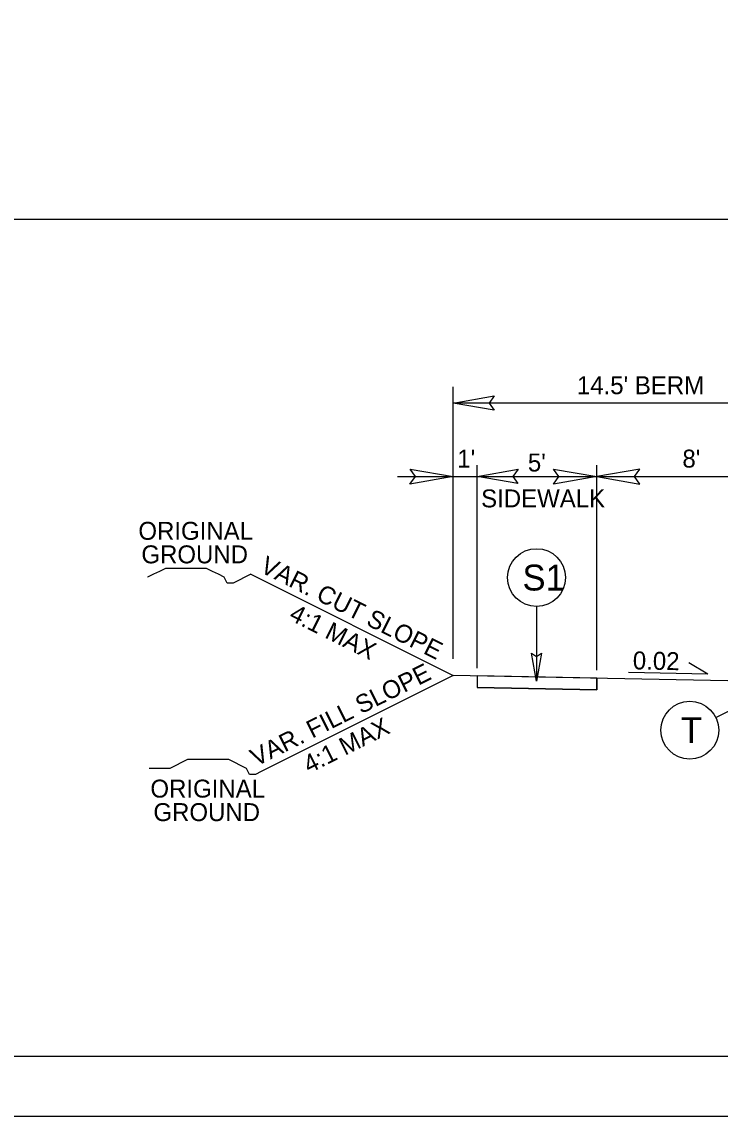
# Model space of a CAD drawing. Extents: x 1487909 to 1489267, y 497866 to 499814.
# Drawn here: x 1488926.44 to 1488955.62, y 498107.09 to 498152.83 of the extents above; entities that cross this region are included whole.
import ezdxf

# ---------------------------------------------------------------- set-up
doc = ezdxf.new("R2010")
doc.units = 0
for name, color, linetype in [('Prop Conc 4in Sidewalk', 7, 'Continuous'), ('Prop Dimension', 7, 'Continuous'), ('Prop Dimension Text', 7, 'Continuous'), ('Prop Shade Light', 7, 'Continuous'), ('Prop Terminator CELL', 7, 'Continuous'), ('Scratch_Level_1', 7, 'Continuous'), ('Sheet Plot Border Outside CELL', 7, 'Continuous'), ('Sheet Typical CELL', 7, 'Continuous'), ('Typical Hinge Slope Arterial CELL', 7, 'Continuous'), ('Typical ID Circle CELL', 7, 'Continuous'), ('Typical Pavement Slope CELL', 7, 'Continuous'), ('Typical Pavement Slope Information CELL', 7, 'Continuous'), ('Typical Terminator CELL', 7, 'Continuous'), ('Typical Text ID Circle CELL', 7, 'Continuous')]:
    doc.layers.add(name, color=color, linetype=linetype)

msp = doc.modelspace()

# ---------------------------------------------------------------- linework, layer by layer
at = {"layer": 'Prop Conc 4in Sidewalk'}
for p, q in [((1488950.464, 498125.387), (1488945.464, 498125.487)), ((1488945.464, 498125.487), (1488945.464, 498125.005)), ((1488950.464, 498124.905), (1488945.464, 498125.005)), ((1488950.464, 498125.387), (1488950.464, 498124.905))]:
    msp.add_line(p, q, dxfattribs=at)
at = {"layer": 'Prop Dimension'}
for p, q in [((1488944.464, 498126.203), (1488944.464, 498137.572)), ((1488958.964, 498136.891), (1488944.464, 498136.891)), ((1488945.464, 498125.808), (1488945.464, 498134.293)), ((1488950.464, 498125.73), (1488950.464, 498134.293)), ((1488942.133, 498133.822), (1488944.464, 498133.822)), ((1488944.464, 498133.822), (1488945.464, 498133.822)), ((1488945.464, 498133.822), (1488950.464, 498133.822)), ((1488950.464, 498133.822), (1488958.464, 498133.822))]:
    msp.add_line(p, q, dxfattribs=at)
at = {"layer": 'Prop Shade Light'}
for p, q in [((1488950.464, 498125.387), (1488945.464, 498125.487)), ((1488945.464, 498125.487), (1488945.464, 498125.005)), ((1488945.464, 498125.005), (1488950.464, 498124.905)), ((1488950.464, 498124.905), (1488950.464, 498125.387))]:
    msp.add_line(p, q, dxfattribs=at)
at = {"layer": 'Prop Terminator CELL'}
for points in [[(1488946.174, 498136.597), (1488944.464, 498136.891), (1488946.183, 498137.195), (1488945.965, 498136.891)], [(1488942.664, 498134.132), (1488944.464, 498133.822), (1488942.654, 498133.502), (1488942.884, 498133.822)], [(1488947.174, 498133.528), (1488945.464, 498133.822), (1488947.183, 498134.126), (1488946.965, 498133.822)], [(1488948.664, 498134.132), (1488950.464, 498133.822), (1488948.654, 498133.502), (1488948.884, 498133.822)], [(1488952.264, 498134.132), (1488950.464, 498133.822), (1488952.274, 498133.502), (1488952.044, 498133.822)]]:
    msp.add_lwpolyline(points, close=True, dxfattribs=at)
at = {"layer": 'Scratch_Level_1'}
msp.add_line((1488899.964, 498144.587), (1489049.964, 498144.587), dxfattribs=at)
at = {"layer": 'Sheet Plot Border Outside CELL'}
msp.add_lwpolyline([(1489051.664, 498217.087), (1488883.264, 498217.087), (1488883.264, 498107.087), (1489051.664, 498107.087)], close=True, dxfattribs=at)
at = {"layer": 'Sheet Typical CELL'}
msp.add_lwpolyline([(1489049.964, 498214.587), (1488899.964, 498214.587), (1488899.964, 498109.587), (1489049.964, 498109.587)], close=True, dxfattribs=at)
at = {"layer": 'Typical Hinge Slope Arterial CELL'}
for p, q in [((1488936.006, 498129.736), (1488944.464, 498125.507)), ((1488944.464, 498125.507), (1488936.441, 498121.495))]:
    msp.add_line(p, q, dxfattribs=at)
for points in [[(1488936.006, 498129.736), (1488935.76, 498129.613), (1488935.513, 498129.489), (1488935.267, 498129.366), (1488935.021, 498129.366), (1488934.897, 498129.613), (1488934.651, 498129.736), (1488934.404, 498129.859), (1488934.158, 498129.982), (1488933.912, 498129.982), (1488933.665, 498129.982), (1488933.419, 498129.982), (1488933.172, 498129.982), (1488932.926, 498129.982), (1488932.68, 498129.982), (1488932.433, 498129.982), (1488932.187, 498129.859), (1488931.941, 498129.736), (1488931.694, 498129.613), (1488931.694, 498129.613), (1488931.694, 498129.613), (1488931.694, 498129.613)], [(1488936.441, 498121.495), (1488936.195, 498121.371), (1488935.948, 498121.371), (1488935.825, 498121.619), (1488935.578, 498121.742), (1488935.332, 498121.865), (1488935.085, 498121.988), (1488934.839, 498121.988), (1488934.593, 498121.988), (1488934.346, 498121.988), (1488934.1, 498121.988), (1488933.854, 498121.988), (1488933.607, 498121.988), (1488933.361, 498121.988), (1488933.115, 498121.865), (1488932.868, 498121.742), (1488932.622, 498121.619), (1488932.252, 498121.619), (1488932.005, 498121.619), (1488931.759, 498121.619)]]:
    msp.add_lwpolyline(points, dxfattribs=at)
at = {"layer": 'Typical ID Circle CELL'}
for p, q in [((1488947.949, 498128.39), (1488947.949, 498125.267)), ((1488955.439, 498123.756), (1488957.097, 498124.581))]:
    msp.add_line(p, q, dxfattribs=at)
for centre in [(1488947.949, 498129.599), (1488954.357, 498123.219)]:
    msp.add_circle(centre, 1.208, dxfattribs=at)
at = {"layer": 'Typical Pavement Slope CELL'}
msp.add_line((1488958.464, 498125.227), (1488944.464, 498125.507), dxfattribs=at)
at = {"layer": 'Typical Pavement Slope Information CELL'}
for q in [(1488954.322, 498126.036), (1488951.789, 498125.629)]:
    msp.add_line((1488955.105, 498125.563), q, dxfattribs=at)
at = {"layer": 'Typical Terminator CELL'}
msp.add_lwpolyline([(1488948.151, 498126.439), (1488947.949, 498125.267), (1488947.741, 498126.445), (1488947.949, 498126.296)], close=True, dxfattribs=at)
msp.add_lwpolyline([(1488948.151, 498126.439), (1488947.949, 498125.267), (1488947.741, 498126.445), (1488947.949, 498126.296)], close=True, dxfattribs=at)

# ---------------------------------------------------------------- texts
at = {"layer": 'Prop Dimension Text'}
for s, p in [("14.5' BERM", (1488949.637, 498137.265)), ("1'", (1488944.638, 498134.196)), ("5'", (1488947.588, 498134.033)), ("8'", (1488954.048, 498134.196)), ('SIDEWALK', (1488945.633, 498132.533))]:
    msp.add_text(s, height=0.75, dxfattribs=at).set_placement(p)
at = {"layer": 'Typical Hinge Slope Arterial CELL'}
for s, p in [('ORIGINAL', (1488931.305, 498131.177)), ('GROUND', (1488931.431, 498130.194)), ('ORIGINAL', (1488931.808, 498120.402)), ('GROUND', (1488931.934, 498119.419))]:
    msp.add_text(s, height=0.75, dxfattribs=at).set_placement(p)
for s, rotation, p in [('VAR. CUT SLOPE', 333.4658, (1488936.346, 498129.855)), ('4:1 MAX', 333.4658, (1488937.558, 498127.853)), ('VAR. FILL SLOPE', 26.5342, (1488936.226, 498121.689)), ('4:1 MAX', 26.5342, (1488938.44, 498121.397))]:
    msp.add_text(s, height=0.75, rotation=rotation, dxfattribs=at).set_placement(p)
at = {"layer": 'Typical Pavement Slope Information CELL'}
msp.add_text('0.02', height=0.75, rotation=358.8543, dxfattribs=at).set_placement((1488951.969, 498125.764))
at = {"layer": 'Typical Text ID Circle CELL'}
for s, height, p in [('S1', 1.0817, (1488947.362, 498129.058)), ('T', 1.082, (1488953.982, 498122.678))]:
    msp.add_text(s, height=height, dxfattribs=at).set_placement(p)

doc.saveas('drawing.dxf')
